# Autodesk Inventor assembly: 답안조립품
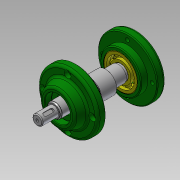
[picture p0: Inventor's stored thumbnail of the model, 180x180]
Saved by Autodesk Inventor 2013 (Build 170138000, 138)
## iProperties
Created: 2018-10
Part Number: 답안조립품
Document SubType Name: Assembly
Designer: hana-cad36
Author: hana-cad36
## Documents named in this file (6)
- C:\Documents and Settings\hana-cad36\바탕 화면\481007V1039\답안조립품.iam
- C:\Documents and Settings\hana-cad36\바탕 화면\481007V1039\본체.ipt
- C:\Documents and Settings\hana-cad36\바탕 화면\481007V1039\베어링 17 x 40 x 12.ipt
- C:\Documents and Settings\hana-cad36\바탕 화면\481007V1039\앞커버.ipt
- C:\Documents and Settings\hana-cad36\바탕 화면\481007V1039\뒤커버.ipt
- C:\Documents and Settings\hana-cad36\바탕 화면\481007V1039\편심축.ipt
